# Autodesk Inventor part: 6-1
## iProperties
Author: Administrator
Created: 2001-02
Part Number: 6-1
Document SubType Name: Modeling
Designer: Administrator
Control State: 0
Master: False
Checked Out: False
PropertySet Name: Design Tracking Control
Shininess: 20.0
PropertySet Name: _Private Model Information
Density: 0.0
Volumn: 0.0
Area: 0.0
PropertySet Name: Model Information
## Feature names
1. Extrusion1
2. Extrusion2
3. Extrusion3
4. Extrusion4
5. Mirror1
6. Hole1
